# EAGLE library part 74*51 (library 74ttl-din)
AND-OR-INVERT gates
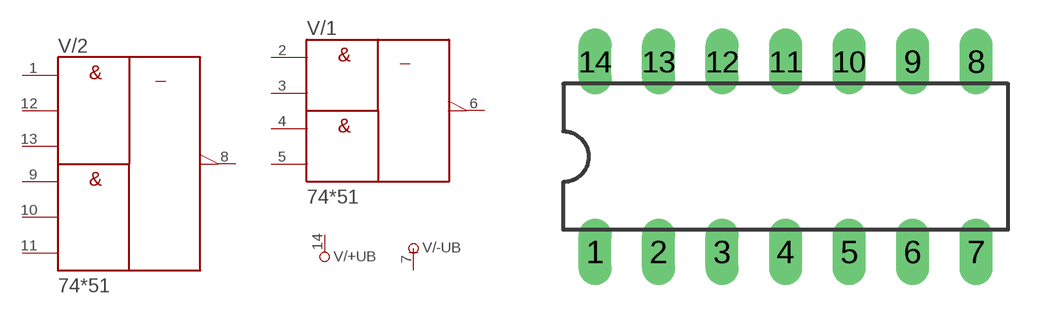
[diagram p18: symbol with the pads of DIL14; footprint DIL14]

Designator prefix V; gates /+UB=+UB /-UB=-UB /1=51_2 /2=51_1

## 7451N  [DIL14]
1  /2:A  in
2  /1:A  in
3  /1:B  in
4  /1:C  in
5  /1:D  in
6  /1:Y  out
7  /-UB:-UB  pwr
8  /2:Y  out
9  /2:D  in
10  /2:E  in
11  /2:F  in
12  /2:B  in
13  /2:C  in
14  /+UB:+UB  pwr

## Footprint DIL14 (pad centres in mm)
Dual In Line Package
drill 0.813 long: 1 -7.62,-3.81; 2 -5.08,-3.81; 3 -2.54,-3.81; 4 0,-3.81; 5 2.54,-3.81; 6 5.08,-3.81; 7 7.62,-3.81; 8 7.62,3.81; 9 5.08,3.81; 10 2.54,3.81; 11 0,3.81; 12 -2.54,3.81; 13 -5.08,3.81; 14 -7.62,3.81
